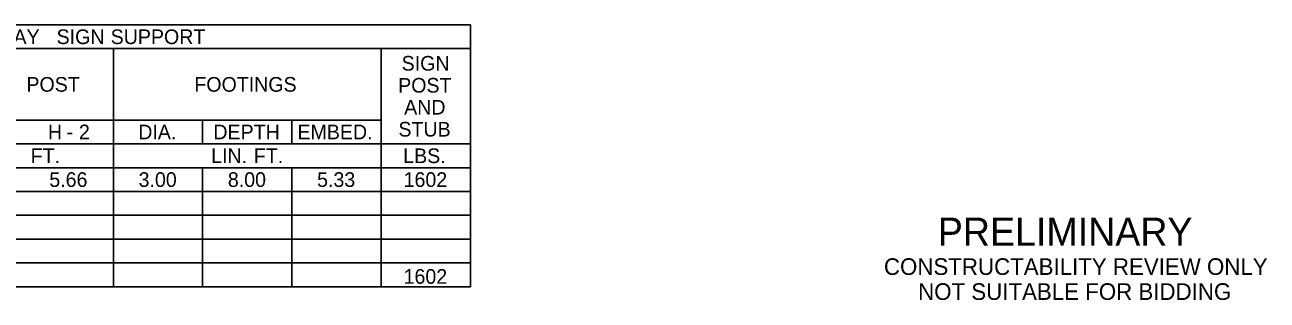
# Model space of a CAD drawing. Extents: x 229 to 4210, y 35 to 1715.
# Drawn here: x 2842 to 3351, y 1133 to 1246 of the extents above; entities that cross this region are included whole.
import ezdxf

# ---------------------------------------------------------------- set-up
doc = ezdxf.new("R2010")
doc.units = 0
doc.layers.add('B_Concrete hidden', color=7, linetype='Continuous')
doc.layers.add('Default', color=7, linetype='Continuous')

msp = doc.modelspace()

# ---------------------------------------------------------------- linework, layer by layer
at = {"layer": 'Default'}
for p, q in [((2347.33, 1245.71), (3024.95, 1245.71)), ((3024.95, 1138.46), (3024.95, 1245.71)), ((3024.95, 1138.46), (3024.95, 1245.71)), ((2659.33, 1235.96), (3024.95, 1235.96)), ((2878.7, 1206.71), (2878.7, 1235.96)), ((2878.7, 1138.46), (2878.7, 1235.96)), ((2988.39, 1138.46), (2988.39, 1235.96)), ((2732.45, 1206.71), (2988.39, 1206.71)), ((2915.26, 1196.96), (2915.26, 1206.71)), ((2951.83, 1196.96), (2951.83, 1206.71)), ((2659.33, 1196.96), (3024.95, 1196.96)), ((2842.14, 1196.96), (2988.39, 1196.96)), ((2878.7, 1148.21), (2878.7, 1196.96)), ((2988.39, 1196.96), (3024.95, 1196.96)), ((2347.33, 1187.21), (3024.95, 1187.21)), ((2622.76, 1187.21), (3024.95, 1187.21)), ((2915.26, 1148.21), (2915.26, 1187.21)), ((2915.26, 1138.46), (2915.26, 1187.21)), ((2951.83, 1148.21), (2951.83, 1187.21)), ((2951.83, 1138.46), (2951.83, 1187.21)), ((2988.39, 1148.21), (2988.39, 1187.21)), ((2347.33, 1177.46), (3024.95, 1177.46)), ((2347.33, 1167.71), (3024.95, 1167.71)), ((2347.33, 1157.96), (3024.95, 1157.96)), ((2347.33, 1148.21), (3024.95, 1148.21)), ((2347.33, 1148.21), (3024.95, 1148.21)), ((2347.33, 1138.46), (3024.95, 1138.46))]:
    msp.add_line(p, q, dxfattribs=at)

# ---------------------------------------------------------------- texts
at = {"layer": 'B_Concrete hidden'}
for s, height, p in [('PRELIMINARY', 11.508, (3216.36, 1155.22)), ('CONSTRUCTABILITY REVIEW ONLY', 6.823, (3194.29, 1143.28)), ('NOT SUITABLE FOR BIDDING', 6.823, (3208.29, 1133.05))]:
    msp.add_text(s, height=height, rotation=0, dxfattribs=at).set_placement(p)
at = {"layer": 'Default'}
for s, p in [(' BREAKAWAY', (2795.44, 1237.83)), (' SIGN', (2853.21, 1237.83)), (' SUPPORT', (2875.36, 1237.83)), ('SIGN', (2996.76, 1226.96)), (' POST', (2840.85, 1218.33)), ('FOOTINGS', (2911.86, 1218.33)), ('POST', (2995.34, 1217.96)), ('AND', (2997.8, 1208.96)), ('STUB', (2995.46, 1199.96)), ('H', (2851.9, 1198.83)), (' -', (2857.31, 1198.83)), (' 2', (2862.37, 1198.83)), ('DIA.', (2888.89, 1198.83)), ('DEPTH', (2919.66, 1198.83)), ('EMBED.', (2954.09, 1198.83)), (' FT.', (2842.61, 1189.08)), ('LIN.', (2918.76, 1189.08)), (' FT.', (2934.01, 1189.08)), ('LBS.', (2997.41, 1189.08)), ('5.66', (2852.46, 1179.33)), ('3.00', (2889.03, 1179.33)), ('8.00', (2925.59, 1179.33)), ('5.33', (2962.14, 1179.33)), ('1602', (2997.57, 1179.33)), ('1602', (2997.56, 1139.66))]:
    msp.add_text(s, height=6, dxfattribs=at).set_placement(p)

doc.saveas('drawing.dxf')
